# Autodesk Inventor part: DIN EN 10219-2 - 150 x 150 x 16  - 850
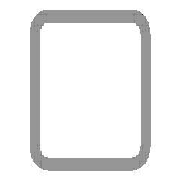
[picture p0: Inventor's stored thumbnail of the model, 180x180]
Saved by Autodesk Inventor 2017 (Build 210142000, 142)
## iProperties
Created: 2017-11
Part Number: DIN EN 10219-2 - 150 x 150 x 16  - 850
Material: Steel, Mild
Description: Cold formed welded structural hollow sections of non-alloy and fine grain structural steel
Document SubType Name: Modeling
Standard: DIN
Designer: iusti
Standard Revision: 2006-07
Standards Organization: DIN
Language: en-US
Size Designation: 150 x 150 x 16
Categories: <MemberInstance><Categories><Category DisplayName="Structural Shapes" InternalName="089c4875-fa83-4c05-b084-43b9cc11f5ed" Mnemonic="GRDR"><CategoryParameter Dis
Stock Number: 150 x 150 x 16
Mass: 49891.9 g
Surface Area: 8094.11 cm^2
Volume: 6355.65 cm^3
Density: 7.85 g/cm^3
Appearance: Semi-Polished
_CCFamilyMember: 76
_CCFamilyDisplayName: DIN EN 10219-2 (Square Hollow Section - Cold Formed) - Cold formed welded structural hollow sections of non-alloy and fine grain structural steel
_FrameMemberDoc: Frame Member File
_Version: 15.0.0
_GetPNFromCC: 1
IsCustomPart: 1
G_L: 850.000 mm
G_W: 150.000 mm
G_H: 150.000 mm
+A639C769-3126-41A6-9F80-CB71605C9A57+CUTDETAIL1: Cut
+C3782257-2068-46F1-A1C7-ECFA59CBB29E+CUTDETAIL2: Cut
Author: iusti
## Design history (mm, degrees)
node "Start plane"
node "End plane"
sketch "Sketch"
  geometry: L1 (-75, -27)-(-75, 27); L2 (-27, 75)-(27, 75); L3 (75, 27)-(75, -27); L4 (27, -75)-(-27, -75); L5 (-27, 59)-(27, 59); L6 (59, 27)-(59, -27); L7 (27, -59)-(-27, -59); L8 (-59, -27)-(-59, 27); L9 (0, 153.918)-(0, -153.918) reference; L10 (-153.918, 0)-(153.918, 0) reference; A1 r 48 centre (-27, -27) between (-75, -27) and (-27, -75); A2 r 48 centre (-27, 27) between (-27, 75) and (-75, 27); A3 r 48 centre (27, 27) between (75, 27) and (27, 75); A4 r 48 centre (27, -27) between (27, -75) and (75, -27); A5 r 32 centre (-27, 27) between (-27, 59) and (-59, 27); A6 r 32 centre (27, 27) between (59, 27) and (27, 59); A7 r 32 centre (27, -27) between (27, -59) and (59, -27); A8 r 32 centre (-27, -27) between (-59, -27) and (-27, -59)
  constraints: 16 end point, 16 point on circle, 8 centre point, 8 tangent, 4 parallel, 3 equal radius, 2 perpendicular, 7 other
  dimensions: "d7" = 48 radius of A1 (= G_IR); "d10" = 150 distance between parallel lines of L2 L4 (= G_H); "d11" = 150 distance between parallel lines of L1 L3 (= G_W); "d12" = 16 distance between parallel lines of L3 L6 (= G_T); "d15" = 75 distance between parallel lines of L2 L10 (= 0.5 x d10); "d16" = 75 distance between parallel lines of L9 L3 (= 0.5 x d11)
extrude "Body" new body sketch "Sketch" stored distance "d3" = 850 (= G_L); taper "d4" = 0 deg
node "Driven Length"
  sketch "Sketch3"
    geometry: L1 (0, 0)-(10, 0) reference
    constraints: 2 end point, 1 horizontal
  workplane "Work Plane3"
  sketch "Sketch4"
    geometry: L1 (-2, 75)-(12, 75) reference; L2 (-2, 925)-(12, 925) reference
    dimensions: "d18" = 850 distance between parallel lines of L1 L2 (derived)
workplane "Work Plane4"
split "Split1"
workplane "Work Plane5"
split "Split2"
body "Solid1"
other parameters: "G_W" = 150 [user parameter; used in 1 equation term], "G_H" = 150 [user parameter; used in 1 equation term], "G_T" = 16 [user parameter; used in 1 equation term], "G_IR" = 48 [user parameter; used in 1 equation term], "G_L" = 850 (= d18) [user parameter; used in 1 equation term], "G_OFFSET_START" = -75 [user parameter; used in 1 equation term], "G_OFFSET_END" = -75 [user parameter; used in 1 equation term], "d13" = 75 (= -G_OFFSET_START), "d14" = 925 (= G_OFFSET_END + B_L), "d17" = 90 deg
